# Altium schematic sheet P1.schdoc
size 297 x 209 mm; Symbol: Drawing-Symbol_A4; @Project Name: ThermalInversion; @Page Count: 1; @Update Date: 2026-10-23; @Create Date: 2026-10-23; @Schematic Name: Schematic1; @Page No: 1; @Page Name: P1; Company: EasyEDA.com; Version: V1.0; Page Size: A4; Device: Drawing-Symbol_A4; @Create Time: 08:45:56; @Update Time: 08:45:56; Border: 1; Width: 1170; Height: 825; Region Start: 1; X Region Count: 6; Y Region Count: 4; Blade Width: 10; Title Block Position: 3; @Board Name: Board1
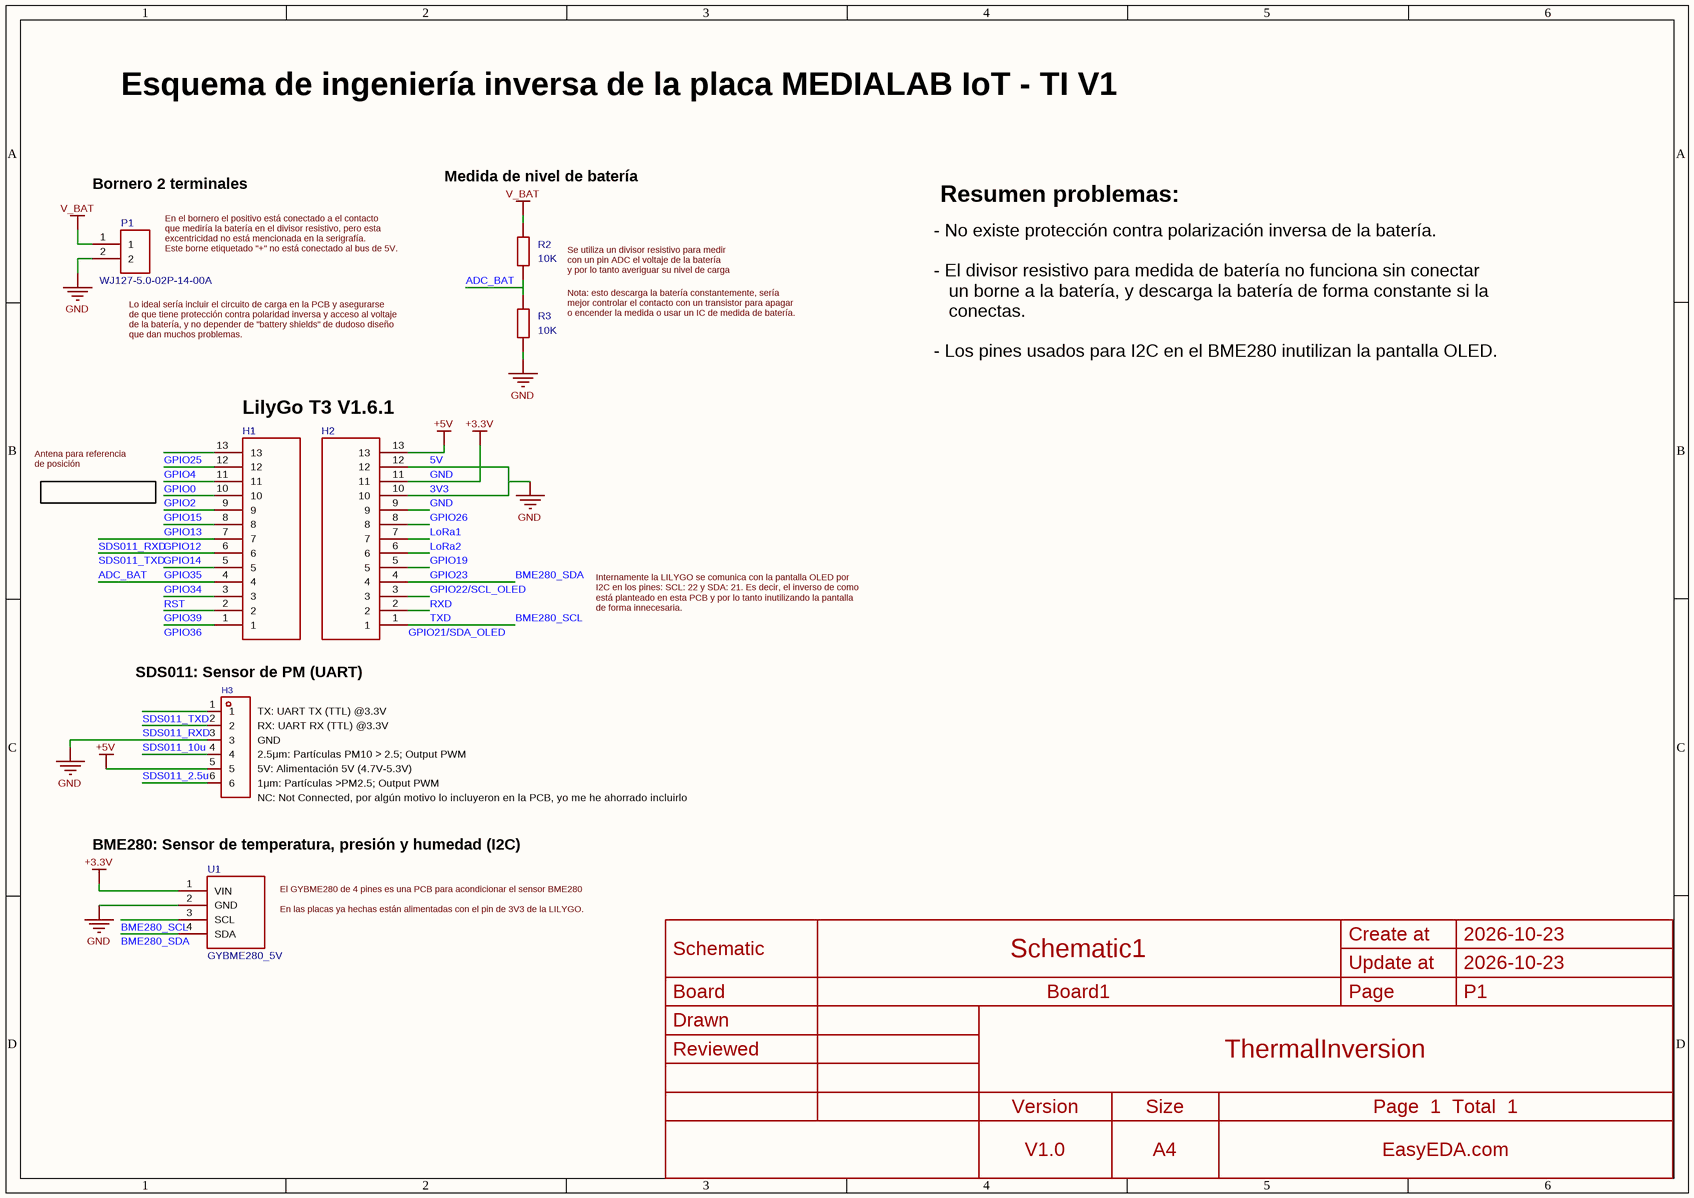
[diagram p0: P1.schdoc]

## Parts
H1  (no value)  [HDR-F_2.54_1x13]
H2  (no value)  [HDR-F_2.54_1x13]
H3  (no value)  [HDR-TH_6P-P2.54-V-F]
P1  WJ127-5.0-02P-14-00A  [CONN-TH_2P-P5.00_CPC3703CTR]
R2  10K  [R0603]
R3  10K  [R0603]
U1  (no value)  [GYBME280_5V]

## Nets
3V3: H2.11 U1.1(VIN)  [also labelled +3.3V]
5V: H2.13 H3.5  [also labelled +5V]
GND: H2.10 H2.12 H3.3 P1.2 R3.2 U1.2(GND)
V_BAT: P1.1 R2.1
ADC_BAT: H1.4 R2.2 R3.1  [also labelled GPIO34]
BME280_SCL: H2.1 U1.3(SCL)  [also labelled GPIO21/SDA_OLED]
BME280_SDA: H2.4 U1.4(SDA)  [also labelled GPIO22/SCL_OLED]
GPIO0: H1.11
GPIO2: H1.10
GPIO4: H1.12
GPIO12: H1.7 H3.2  [also labelled SDS011_RXD]
GPIO13: H1.8
GPIO14: H1.6 H3.1  [also labelled SDS011_TXD]
GPIO15: H1.9
GPIO19: H2.6
GPIO23: H2.5
GPIO25: H1.13
GPIO26: H2.9
GPIO35: H1.5
GPIO36: H1.1
GPIO39: H1.2
LoRa1: H2.8
LoRa2: H2.7
RST: H1.3
RXD: H2.3
SDS011_2.5u: H3.6
SDS011_10u: H3.4
TXD: H2.2

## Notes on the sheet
- Esquema de ingeniería inversa de la placa MEDIALAB IoT - TI V1
- (near P1) Bornero 2 terminales
- En el bornero el positivo está conectado a el contacto
  que mediría la batería en el divisor resistivo, pero esta
  excentricidad no está mencionada en la serigrafía.
  Este borne etiquetado "+" no está conectado al bus de 5V.
- (near R2) Medida de nivel de batería
- - No existe protección contra polarización inversa de la batería.
  - El divisor resistivo para medida de batería no funciona sin conectar
  un borne a la batería, y descarga la batería de forma constante si la
  conectas.
  - Los pines usados para I2C en el BME280 inutilizan la pantalla OLED.
- Resumen problemas:
- Se utiliza un divisor resistivo para medir
  con un pin ADC el voltaje de la batería
  y por lo tanto averiguar su nivel de carga
- Nota: esto descarga la batería constantemente, sería
  mejor controlar el contacto con un transistor para apagar
  o encender la medida o usar un IC de medida de batería.
- (near H1) Lo ideal sería incluir el circuito de carga en la PCB y asegurarse
  de que tiene protección contra polaridad inversa y acceso al voltaje
  de la batería, y no depender de "battery shields" de dudoso diseño
  que dan muchos problemas.
- LilyGo T3 V1.6.1
- Antena para referencia
  de posición
- Internamente la LILYGO se comunica con la pantalla OLED por
  I2C en los pines: SCL: 22 y SDA: 21. Es decir, el inverso de como
  está planteado en esta PCB y por lo tanto inutilizando la pantalla
  de forma innecesaria.
- SDS011: Sensor de PM (UART)
- (near H3) TX: UART TX (TTL) @3.3V
- (near H3) RX: UART RX (TTL) @3.3V
- (near H3) GND
- (near H3) 2.5μm: Partículas PM10 > 2.5; Output PWM
- (near H3) 5V: Alimentación 5V (4.7V-5.3V)
- (near H3) 1μm: Partículas >PM2.5; Output PWM
- BME280: Sensor de temperatura, presión y humedad (I2C)
- (near H3) NC: Not Connected, por algún motivo lo incluyeron en la PCB, yo me he ahorrado incluirlo
- El GYBME280 de 4 pines es una PCB para acondicionar el sensor BME280
  En las placas ya hechas están alimentadas con el pin de 3V3 de la LILYGO.

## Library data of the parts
H1 H2 = HDR-F_2.54_1x13: Cabecero hembra de 13 pines a 2.54mm; Convert to PCB: yes
H3 = HDR-F_2.54_1x6P: Manufacturer: BOOMELE(博穆精密); Manufacturer Part: 2.54-1*6P母; Symbol: Header-Female-2.54_1x6; ConvertToPcb: yes; ModelId: 72da3eac8a074bb0a56a474e38d1760c0819f05c4eef4c71ace90d822a990e87; ModelTransform: 619.684,94.488,0,0,0,0,0,0,-125.984
P1 = WJ127-5.0-02P-14-00A: Number of Positions or Pins:1x2P Pitch:5mm Color:Green Mounting Type:Through Hole Number of Pins:2P Number of Rows:1 Number of PINs Per Row:2 Screw Specification:M2.5 Current Rating:15A Voltage Rating (Max):250V Wire Gauge - AWG:14~26 Wire Gauge - mm2:1.5; Manufacturer: KANGNEX(康奈克斯电气); Symbol: WJ127-5.0-2P; AddInBom: yes; ModelId: 0c699dafc1fb4759bdee4490ad46ecba0819f05c4eef4c71ace90d822a990e87; ModelTransform: 416.145,318.897,0,0,0,0,-11.811,5.315,-149.606; Number of Positions or Pins: 1x2P; Pitch: 5mm; Number of PINs Per Row: 2; Screw Specification: M2.5; Current Rating: 15A; Voltage Rating (Max): 250V; Wire Gauge - AWG: 14~26; Wire Gauge - mm2: 1.5
R2 R3 = Res_0603: Symbol: Res; 3D Model: 112863783b5b41f1b5254f87eedc79320819f05c4eef4c71ace90d822a990e87; 3D Model Transform: 31.8897,63.7794,0,90,0,0,0,0,0; ConvertToPcb: yes
U1 = GYBME280_5V: PCB con circuito de acondicionamiento para BMP280 con comunicación I2C y alimentación a 5V.; AddInBom: yes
